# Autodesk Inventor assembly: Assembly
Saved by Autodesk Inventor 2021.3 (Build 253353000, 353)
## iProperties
Created: 2022-12
Part Number: Assembly
Document SubType Name: Assembly
Designer: AdminForWorker
Title: Assembly v7
Author: AdminForWorker
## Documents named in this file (4)
- c:\worker\convert-fusion-r07-cosv3\tmp\job-1\248\output\files\02726f4c-9815-42dc-95dc-176fb5068647\Assembly v7.iam
- c:\worker\convert-fusion-r07-cosv3\tmp\job-1\248\output\files\02726f4c-9815-42dc-95dc-176fb5068647\FX29 Load Cell v4.ipt
- c:\worker\convert-fusion-r07-cosv3\tmp\job-1\248\output\files\02726f4c-9815-42dc-95dc-176fb5068647\Enclosure Bottom v1 v7.ipt
- c:\worker\convert-fusion-r07-cosv3\tmp\job-1\248\output\files\02726f4c-9815-42dc-95dc-176fb5068647\Enclosure Top v1 v10.ipt
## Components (3 placed, 3 different names)
1. FX29 Load Cell v4:1
2. Enclosure Bottom v1 v7:1
3. Enclosure Top v1 v10:1
